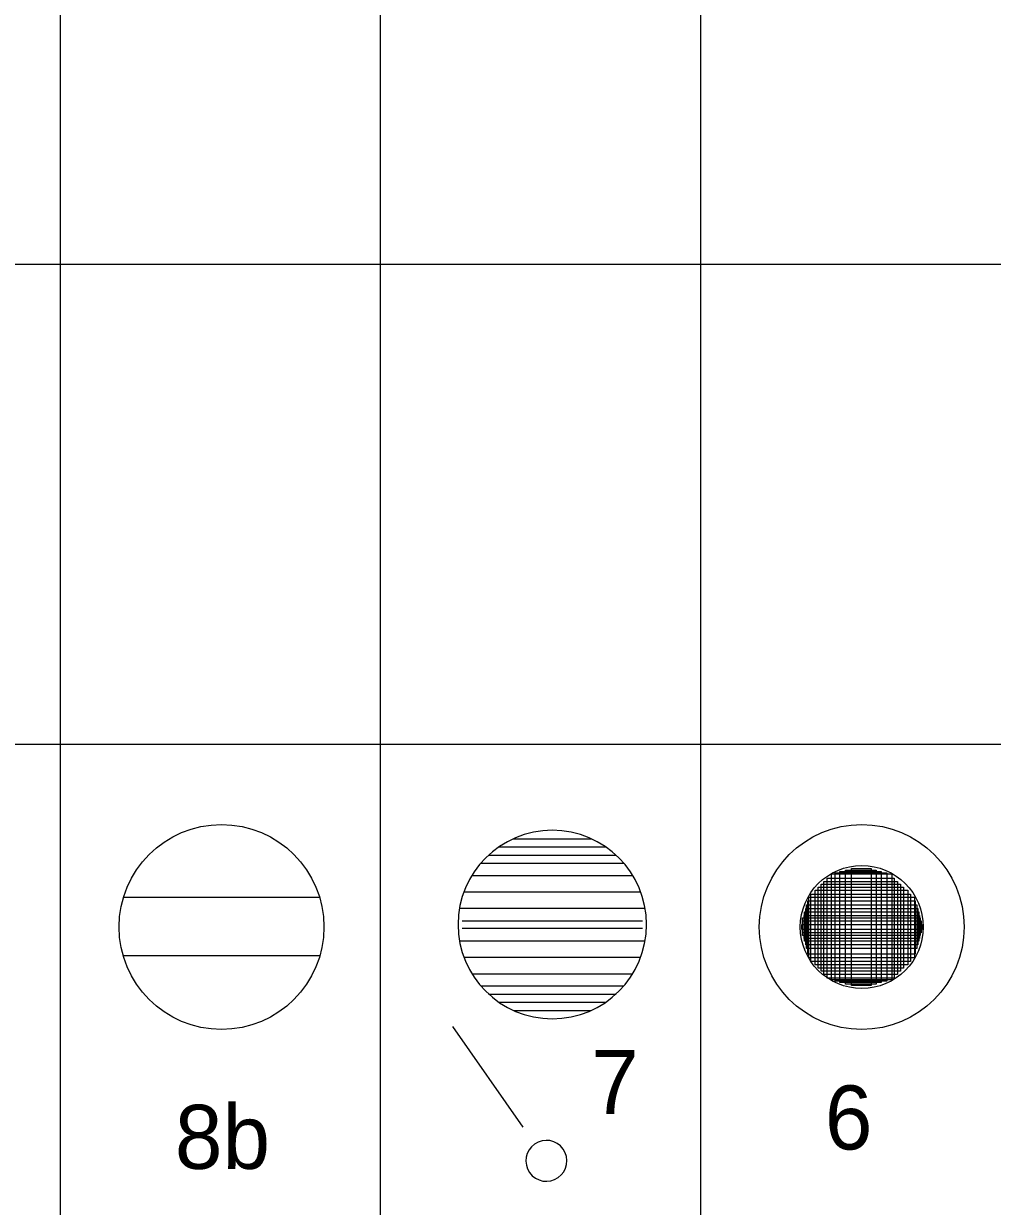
# Model space of a CAD drawing. Extents: x -28 to 822, y 61 to 665.
# Drawn here: x 369.48 to 399.74, y 277.3 to 314.25 of the extents above; entities that cross this region are included whole.
import ezdxf

# ---------------------------------------------------------------- set-up
doc = ezdxf.new("R2010")
doc.units = 0
doc.layers.add('KOLEJIŠTĚ', color=7, linetype='Continuous')

# ---------------------------------------------------------------- blocks, each defined once
blk = doc.blocks.new('HR3')
for radius in [2.5, 1.5]:
    blk.add_circle((0, 0), radius)
blk = doc.blocks.new('ZT72')
at = {"xscale": 0.8, "yscale": 0.8000000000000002}
blk.add_blockref('HR3', (0, 0), dxfattribs=at)
blk = doc.blocks.new('HR6')
for p, q in [((-0.95, 2.095), (0.95, 2.095)), ((-1.304, 1.895), (1.304, 1.895)), ((-1.748, 1.495), (1.748, 1.495)), ((-1.555, 1.695), (1.555, 1.695)), ((-1.962, 1.2), (1.962, 1.2)), ((-2.156, 0.8), (2.156, 0.8)), ((-2.265, 0.4), (2.265, 0.4)), ((-2.2, 0.09), (2.2, 0.09)), ((-2.2, -0.09), (2.2, -0.09)), ((-2.265, -0.4), (2.265, -0.4)), ((-2.156, -0.8), (2.156, -0.8)), ((-1.962, -1.2), (1.962, -1.2)), ((-1.748, -1.495), (1.748, -1.495)), ((-1.555, -1.695), (1.555, -1.695)), ((-1.304, -1.895), (1.304, -1.895)), ((-0.95, -2.095), (0.95, -2.095))]:
    blk.add_line(p, q)
for start, end in [(0, 180), (180, 0)]:
    blk.add_arc((0, 0), 2.3, start, end)
blk = doc.blocks.new('ZT75')
at = {"xscale": 0.8, "yscale": 0.8000000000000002}
blk.add_blockref('HR6', (0, 0), dxfattribs=at)

msp = doc.modelspace()

# ---------------------------------------------------------------- linework, layer by layer
for p, q in [((370.616, 381.738), (370.616, 111.738)), ((380.616, 381.738), (380.616, 111.738)), ((390.616, 381.738), (390.616, 111.738)), ((5.068, 306.738), (540.616, 306.738)), ((5.068, 291.738), (540.616, 291.738)), ((378.72, 286.957), (372.594, 286.957)), ((378.727, 285.126), (372.588, 285.126)), ((382.868, 282.92), (385.071, 279.774))]:
    msp.add_line(p, q)
for points in [[(396.109, 284.246), (395.145, 284.246), (395.145, 287.81), (396.109, 287.81)], [(395.955, 284.201), (395.336, 284.201), (395.336, 287.856), (395.955, 287.856)], [(396.774, 284.546), (394.471, 284.546), (394.471, 287.456), (396.774, 287.456)], [(396.665, 284.437), (394.572, 284.437), (394.572, 287.556), (396.665, 287.556)], [(396.601, 284.383), (394.708, 284.383), (394.708, 287.692), (396.601, 287.692)], [(396.437, 284.337), (394.826, 284.337), (394.826, 287.719), (396.437, 287.719)], [(396.264, 284.292), (394.972, 284.292), (394.972, 287.765), (396.264, 287.765)], [(397.092, 284.846), (394.198, 284.846), (394.198, 287.183), (397.092, 287.183)], [(396.965, 284.746), (394.299, 284.746), (394.299, 287.274), (396.965, 287.274)], [(396.865, 284.646), (394.39, 284.646), (394.39, 287.365), (396.865, 287.365)], [(397.374, 285.355), (393.935, 285.355), (393.935, 286.728), (397.374, 286.728)], [(397.329, 285.183), (393.971, 285.183), (393.971, 286.847), (397.329, 286.847)], [(397.302, 285.064), (394.007, 285.064), (394.007, 286.965), (397.302, 286.965)], [(397.183, 284.955), (394.071, 284.955), (394.071, 287.056), (397.183, 287.056)], [(397.465, 285.674), (393.853, 285.674), (393.853, 286.392), (397.465, 286.392)], [(397.438, 285.583), (393.871, 285.583), (393.871, 286.501), (397.438, 286.501)], [(397.411, 285.474), (393.907, 285.474), (393.907, 286.61), (397.411, 286.61)], [(397.547, 285.956), (393.78, 285.956), (393.78, 286.11), (397.547, 286.11)], [(397.484, 285.765), (393.807, 285.765), (393.807, 286.319), (397.484, 286.319)], [(397.511, 285.846), (393.807, 285.846), (393.807, 286.219), (397.511, 286.219)]]:
    msp.add_lwpolyline(points, close=True)
msp.add_circle((375.657, 286.031), 3.2)
for start, end in [(35, 215), (215, 35)]:
    msp.add_arc((385.805, 278.726), 0.64, start, end)

# ---------------------------------------------------------------- block references
at = {"layer": 'KOLEJIŠTĚ', "xscale": 1.600000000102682, "yscale": 1.600000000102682}
for name, p in [('ZT75', (385.991, 286.107)), ('ZT72', (395.657, 286.031))]:
    msp.add_blockref(name, p, dxfattribs=at)

# ---------------------------------------------------------------- texts
for s, p in [('7', (387.204, 280.19)), ('6', (394.504, 279.081)), ('8b', (374.2, 278.475))]:
    msp.add_text(s, height=2).set_placement(p)

doc.saveas('drawing.dxf')
